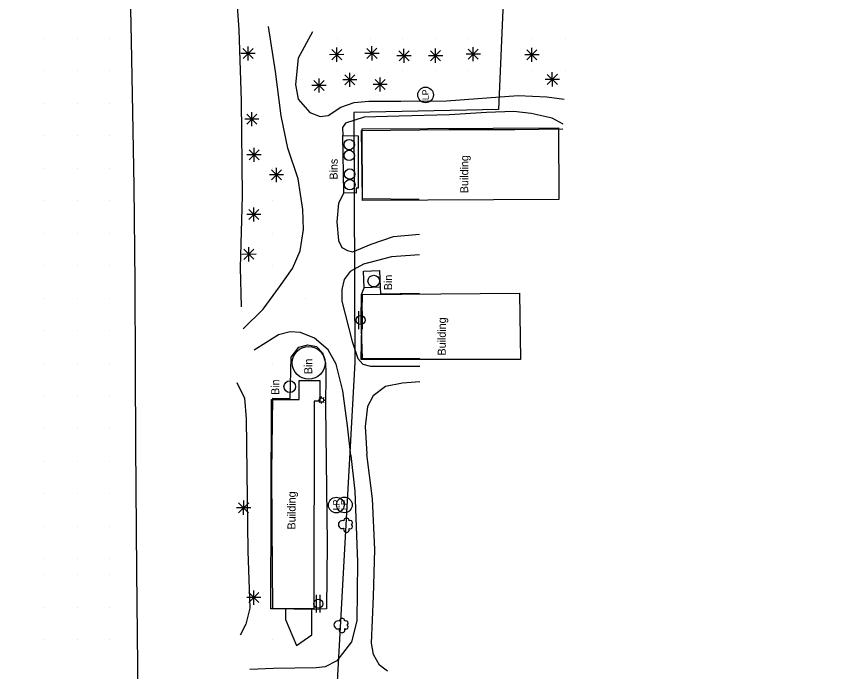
# Model space of a CAD drawing. Extents: x 19528164 to 19545171, y 7585743 to 7602745.
# Drawn here: x 19538887.4 to 19539384.5, y 7590990.4 to 7591393.6 of the extents above; entities that cross this region are included whole.
import ezdxf

# ---------------------------------------------------------------- set-up
doc = ezdxf.new("R2010")
doc.units = 0
for name, color, linetype in [('PhoAgStruc', 7, 'Continuous'), ('PhoBreakLine', 7, 'Continuous'), ('PhoBuilding', 7, 'Continuous'), ('PhoConcreteSlab', 7, 'Continuous'), ('PhoFence', 7, 'Continuous'), ('PhoISAEPoints', 7, 'Continuous'), ('PhoNotesDesign', 7, 'Continuous'), ('PhoSurveyLimits', 7, 'Continuous'), ('PhoVegetation', 7, 'Continuous'), ('SurNaturalCells', 7, 'Continuous'), ('SurROWRail', 7, 'Continuous')]:
    doc.layers.add(name, color=color, linetype=linetype)

msp = doc.modelspace()

# ---------------------------------------------------------------- linework, layer by layer
at = {"layer": 'PhoAgStruc'}
for centre, radius in [((19539092.17, 7591314.62), 3.21), ((19539092.15, 7591307.99), 3.21), ((19539092.49, 7591296.47), 3.21), ((19539092.51, 7591289.96), 3.21), ((19539107.24, 7591230.71), 3.58), ((19539067.23, 7591180.39), 10.06), ((19539055.61, 7591165.75), 3.58)]:
    msp.add_circle(centre, radius, dxfattribs=at)
at = {"layer": 'PhoBreakLine'}
for points in [[(19539025.94, 7591214.81), (19539025.21, 7591239.13), (19539026.55, 7591282.93), (19539025.96, 7591341.48), (19539024.58, 7591385.28), (19539021.31, 7591432.04), (19539020.65, 7591488.25), (19539019.39, 7591531.16), (19539015.09, 7591568.39), (19539005.57, 7591605.31), (19538988.58, 7591634.8), (19538965.78, 7591663.6), (19538941.84, 7591687.62), (19538913.36, 7591707.64), (19538889.81, 7591717.59)], [(19538960.98, 7591129.76), (19538960.69, 7591177.17), (19538960.55, 7591229.68), (19538959.96, 7591288.96), (19538959.08, 7591334.58), (19538958.24, 7591378.21), (19538957.47, 7591418.01), (19538957.15, 7591460.19), (19538956.9, 7591507.6), (19538955.55, 7591540.34), (19538952.92, 7591562.95), (19538946.91, 7591580.96), (19538929.63, 7591609.56), (19538905.04, 7591635.92), (19538883.9, 7591650.01), (19538863.93, 7591658.15), (19538827.45, 7591669.97), (19538802.9, 7591674.09), (19538770.4, 7591676.06), (19538725.84, 7591674.84), (19538709.43, 7591674.53)], [(19539135.19, 7591280.88), (19539100.27, 7591281.24), (19539099.61, 7591323.38), (19539153.31, 7591323.86), (19539193.88, 7591324), (19539223.49, 7591324.32)], [(19539135.53, 7591182.89), (19539100.31, 7591183.14), (19539099.55, 7591207.12), (19539099.66, 7591222.34), (19539101.3, 7591226.6)], [(19539111.2, 7591227.01), (19539111.4, 7591222.94), (19539135.39, 7591223.21)], [(19539023.1, 7591168.25), (19539027.81, 7591158.74), (19539028.81, 7591145.93), (19539029.73, 7591064.5), (19539031.03, 7591029.45), (19539028.63, 7591019.72), (19539025.11, 7591012.9)], [(19538977.84, 7590689.62), (19538970.79, 7590726.93), (19538967.2, 7590763.47), (19538965.07, 7590800.31), (19538964.71, 7590837.65), (19538964.26, 7590895.44), (19538962.68, 7590956), (19538961.54, 7591052.07), (19538960.98, 7591129.76)]]:
    msp.add_lwpolyline(points, dxfattribs=at)
msp.add_lwpolyline([(19539070.74, 7591028.77), (19539045.14, 7591029.2), (19539044.87, 7591080.32), (19539044.62, 7591113.49), (19539045.16, 7591158.6), (19539055.92, 7591158.5), (19539056.4, 7591183.88), (19539061.07, 7591189.94), (19539066.64, 7591191.57), (19539072, 7591190.43), (19539075.63, 7591186.46), (19539077.6, 7591180.49), (19539077.82, 7591174.33), (19539077.58, 7591153.41), (19539078.61, 7591069.5), (19539078.22, 7591029.19)], close=True, dxfattribs=at)
at = {"layer": 'PhoBuilding'}
for points in [[(19539100.07, 7591324.27), (19539220.84, 7591324.99), (19539221.1, 7591280.9), (19539100.34, 7591280.18)], [(19539044.04, 7591029.12), (19539044.31, 7591157.92), (19539061.41, 7591157.89), (19539061.43, 7591169.52), (19539074.01, 7591169.5), (19539073.98, 7591156.75), (19539070.58, 7591156.76), (19539070.31, 7591029.07)]]:
    msp.add_lwpolyline(points, close=True, dxfattribs=at)
msp.add_lwpolyline([(19539100.08, 7591222.44), (19539196.77, 7591223.24), (19539197.34, 7591182.38), (19539099.5, 7591182.42), (19539100.34, 7591222.44)], dxfattribs=at)
at = {"layer": 'PhoConcreteSlab'}
for points in [[(19539088.76, 7591284.98), (19539088.21, 7591320.31), (19539097.61, 7591319.96), (19539097.72, 7591287.73), (19539096.49, 7591287.81), (19539096.33, 7591284.66)], [(19539101.3, 7591226.6), (19539101.01, 7591236.8), (19539110.78, 7591237.26), (19539111.2, 7591227.01)]]:
    msp.add_lwpolyline(points, close=True, dxfattribs=at)
at = {"layer": 'PhoFence'}
msp.add_lwpolyline([(19539052.91, 7591029.11), (19539052.93, 7591022.61), (19539059.73, 7591006.67), (19539069.17, 7591013.17), (19539069.16, 7591029.07)], dxfattribs=at)
at = {"layer": 'PhoISAEPoints'}
for p, q in [((19538905, 7591380), (19538905, 7591380)), ((19538925, 7591380), (19538925, 7591380)), ((19538945, 7591380), (19538945, 7591380)), ((19539085, 7591380), (19539085, 7591380)), ((19539105, 7591380), (19539105, 7591380)), ((19539125, 7591380), (19539125, 7591380)), ((19539145, 7591380), (19539145, 7591380)), ((19539165, 7591380), (19539165, 7591380)), ((19539185, 7591380), (19539185, 7591380)), ((19539205, 7591380), (19539205, 7591380)), ((19539225, 7591380), (19539225, 7591380)), ((19538905, 7591360), (19538905, 7591360)), ((19538925, 7591360), (19538925, 7591360)), ((19538945, 7591360), (19538945, 7591360)), ((19539085, 7591360), (19539085, 7591360)), ((19539105, 7591360), (19539105, 7591360)), ((19539125, 7591360), (19539125, 7591360)), ((19539145, 7591360), (19539145, 7591360)), ((19539165, 7591360), (19539165, 7591360)), ((19539185, 7591360), (19539185, 7591360)), ((19539205, 7591360), (19539205, 7591360)), ((19539225, 7591360), (19539225, 7591360)), ((19538905, 7591340), (19538905, 7591340)), ((19538925, 7591340), (19538925, 7591340)), ((19538945, 7591340), (19538945, 7591340)), ((19538905, 7591320), (19538905, 7591320)), ((19538925, 7591320), (19538925, 7591320)), ((19538945, 7591320), (19538945, 7591320)), ((19538905, 7591300), (19538905, 7591300)), ((19538925, 7591300), (19538925, 7591300)), ((19538945, 7591300), (19538945, 7591300)), ((19539045, 7591300), (19539045, 7591300)), ((19538905, 7591280), (19538905, 7591280)), ((19538925, 7591280), (19538925, 7591280)), ((19538945, 7591280), (19538945, 7591280)), ((19539045, 7591280), (19539045, 7591280)), ((19538905, 7591260), (19538905, 7591260)), ((19538925, 7591260), (19538925, 7591260)), ((19538945, 7591260), (19538945, 7591260)), ((19539045, 7591260), (19539045, 7591260)), ((19538905, 7591240), (19538905, 7591240)), ((19538925, 7591240), (19538925, 7591240)), ((19538945, 7591240), (19538945, 7591240)), ((19539045, 7591240), (19539045, 7591240)), ((19538905, 7591220), (19538905, 7591220)), ((19538925, 7591220), (19538925, 7591220)), ((19538945, 7591220), (19538945, 7591220)), ((19539065, 7591220), (19539065, 7591220)), ((19538905, 7591200), (19538905, 7591200)), ((19538925, 7591200), (19538925, 7591200)), ((19538945, 7591200), (19538945, 7591200)), ((19538905, 7591180), (19538905, 7591180)), ((19538925, 7591180), (19538925, 7591180)), ((19538945, 7591180), (19538945, 7591180)), ((19539045, 7591180), (19539045, 7591180)), ((19538905, 7591160), (19538905, 7591160)), ((19538925, 7591160), (19538925, 7591160)), ((19538945, 7591160), (19538945, 7591160)), ((19538905, 7591140), (19538905, 7591140)), ((19538925, 7591140), (19538925, 7591140)), ((19538945, 7591140), (19538945, 7591140)), ((19538905, 7591120), (19538905, 7591120)), ((19538925, 7591120), (19538925, 7591120)), ((19538945, 7591120), (19538945, 7591120)), ((19538905, 7591100), (19538905, 7591100)), ((19538925, 7591100), (19538925, 7591100)), ((19538945, 7591100), (19538945, 7591100)), ((19538905, 7591080), (19538905, 7591080)), ((19538925, 7591080), (19538925, 7591080)), ((19538945, 7591080), (19538945, 7591080)), ((19538905, 7591060), (19538905, 7591060)), ((19538925, 7591060), (19538925, 7591060)), ((19538945, 7591060), (19538945, 7591060)), ((19538905, 7591050), (19538905, 7591050)), ((19538925, 7591050), (19538925, 7591050)), ((19538945, 7591050), (19538945, 7591050)), ((19538905, 7591030), (19538905, 7591030)), ((19538925, 7591030), (19538925, 7591030)), ((19538945, 7591030), (19538945, 7591030)), ((19538905, 7591010), (19538905, 7591010)), ((19538925, 7591010), (19538925, 7591010)), ((19538945, 7591010), (19538945, 7591010)), ((19539045, 7591010), (19539045, 7591010)), ((19539065, 7591010), (19539065, 7591010))]:
    msp.add_line(p, q, dxfattribs=at)
at = {"layer": 'PhoSurveyLimits'}
msp.add_lwpolyline([(19543262.35, 7595683.22), (19543257.95, 7595379.65), (19542419.97, 7595255.07), (19541879.23, 7595109.17), (19539317.07, 7592404.33), (19539317.07, 7592404.33), (19539199.99, 7591704.87), (19539183.97, 7591336.2), (19539095.01, 7591334.37), (19539095.54, 7591180.74), (19539068.71, 7590695.4), (19538920.46, 7590698.41), (19538798.64, 7591142.79), (19538688.52, 7591615.61), (19537853.91, 7591634.47), (19537374.94, 7591324.13)], dxfattribs=at)
at = {"layer": 'PhoVegetation'}
for p, q in [((19539029.96, 7591366.25), (19539029.93, 7591375)), ((19539084.47, 7591365.55), (19539084.44, 7591374.3)), ((19539106.16, 7591366.35), (19539106.13, 7591375.1)), ((19539168.41, 7591365.88), (19539168.38, 7591374.63)), ((19539204.47, 7591365.46), (19539204.44, 7591374.21)), ((19539034.32, 7591370.64), (19539025.57, 7591370.61)), ((19539033.05, 7591367.54), (19539026.84, 7591373.71)), ((19539033.02, 7591373.73), (19539026.86, 7591367.52)), ((19539029.94, 7591370.63), (19539029.94, 7591370.63)), ((19539088.83, 7591369.94), (19539080.09, 7591369.91)), ((19539087.56, 7591366.84), (19539081.36, 7591373.01)), ((19539087.54, 7591373.03), (19539081.38, 7591366.82)), ((19539084.46, 7591369.92), (19539084.46, 7591369.92)), ((19539110.52, 7591370.74), (19539101.77, 7591370.71)), ((19539109.25, 7591367.64), (19539103.04, 7591373.8)), ((19539109.22, 7591373.83), (19539103.06, 7591367.62)), ((19539106.14, 7591370.72), (19539106.14, 7591370.72)), ((19539130.21, 7591369.23), (19539121.46, 7591369.2)), ((19539128.94, 7591366.14), (19539122.73, 7591372.3)), ((19539128.92, 7591372.32), (19539122.76, 7591366.11)), ((19539125.85, 7591364.84), (19539125.82, 7591373.59)), ((19539125.84, 7591369.22), (19539125.84, 7591369.22)), ((19539149.6, 7591369.3), (19539140.85, 7591369.27)), ((19539148.33, 7591366.2), (19539142.12, 7591372.37)), ((19539148.31, 7591372.39), (19539142.15, 7591366.18)), ((19539145.24, 7591364.91), (19539145.21, 7591373.66)), ((19539145.23, 7591369.28), (19539145.23, 7591369.28)), ((19539172.77, 7591370.27), (19539164.02, 7591370.24)), ((19539171.5, 7591367.18), (19539165.3, 7591373.34)), ((19539171.48, 7591373.36), (19539165.32, 7591367.16)), ((19539168.4, 7591370.26), (19539168.4, 7591370.26)), ((19539208.83, 7591369.85), (19539200.09, 7591369.82)), ((19539207.56, 7591366.75), (19539201.36, 7591372.91)), ((19539207.54, 7591372.93), (19539201.38, 7591366.73)), ((19539204.46, 7591369.83), (19539204.46, 7591369.83)), ((19539217.03, 7591350.36), (19539217, 7591359.11)), ((19539073.61, 7591346.59), (19539073.58, 7591355.34)), ((19539096.88, 7591354.49), (19539088.13, 7591354.46)), ((19539095.61, 7591351.39), (19539089.4, 7591357.56)), ((19539095.59, 7591357.58), (19539089.43, 7591351.37)), ((19539092.52, 7591350.1), (19539092.49, 7591358.85)), ((19539092.51, 7591354.47), (19539092.51, 7591354.47)), ((19539114.29, 7591348.52), (19539108.08, 7591354.69)), ((19539114.27, 7591354.71), (19539108.1, 7591348.5)), ((19539111.2, 7591347.23), (19539111.17, 7591355.98)), ((19539221.39, 7591354.75), (19539212.64, 7591354.72)), ((19539220.12, 7591351.66), (19539213.91, 7591357.82)), ((19539220.09, 7591357.84), (19539213.93, 7591351.63)), ((19539217.01, 7591354.74), (19539217.01, 7591354.74)), ((19539077.97, 7591350.98), (19539069.22, 7591350.95)), ((19539076.7, 7591347.88), (19539070.49, 7591354.05)), ((19539076.68, 7591354.07), (19539070.52, 7591347.86)), ((19539073.6, 7591350.96), (19539073.6, 7591350.96)), ((19539115.56, 7591351.62), (19539106.81, 7591351.59)), ((19539111.19, 7591351.6), (19539111.19, 7591351.6)), ((19539032.31, 7591325.91), (19539032.28, 7591334.66)), ((19539036.67, 7591330.3), (19539027.92, 7591330.27)), ((19539035.4, 7591327.2), (19539029.19, 7591333.36)), ((19539035.38, 7591333.38), (19539029.21, 7591327.18)), ((19539032.3, 7591330.28), (19539032.3, 7591330.28)), ((19539036.75, 7591305.26), (19539030.54, 7591311.43)), ((19539036.73, 7591311.45), (19539030.57, 7591305.24)), ((19539033.66, 7591303.97), (19539033.63, 7591312.72)), ((19539038.02, 7591308.36), (19539029.27, 7591308.33)), ((19539033.65, 7591308.34), (19539033.65, 7591308.34)), ((19539047.48, 7591291.6), (19539047.45, 7591300.35)), ((19539051.84, 7591295.99), (19539043.09, 7591295.96)), ((19539050.57, 7591292.89), (19539044.36, 7591299.06)), ((19539050.55, 7591299.08), (19539044.39, 7591292.87)), ((19539047.47, 7591295.98), (19539047.47, 7591295.98)), ((19539036.62, 7591268.52), (19539030.42, 7591274.69)), ((19539036.6, 7591274.71), (19539030.44, 7591268.5)), ((19539033.54, 7591267.23), (19539033.5, 7591275.98)), ((19539037.89, 7591271.62), (19539029.15, 7591271.59)), ((19539033.52, 7591271.6), (19539033.52, 7591271.6)), ((19539033.61, 7591244.06), (19539027.4, 7591250.23)), ((19539033.58, 7591250.25), (19539027.42, 7591244.04)), ((19539030.52, 7591242.77), (19539030.49, 7591251.52)), ((19539034.87, 7591247.16), (19539026.13, 7591247.13)), ((19539030.5, 7591247.14), (19539030.5, 7591247.14)), ((19539027.21, 7591086.9), (19539027.26, 7591095.65)), ((19539031.61, 7591091.25), (19539022.86, 7591091.3)), ((19539030.35, 7591094.35), (19539024.13, 7591088.2)), ((19539030.31, 7591088.17), (19539024.16, 7591094.39)), ((19539027.24, 7591091.28), (19539027.24, 7591091.28)), ((19539037.86, 7591036.03), (19539029.11, 7591036.07)), ((19539036.59, 7591039.13), (19539030.38, 7591032.97)), ((19539036.56, 7591032.94), (19539030.41, 7591039.16)), ((19539033.46, 7591031.68), (19539033.51, 7591040.42)), ((19539033.49, 7591036.05), (19539033.49, 7591036.05))]:
    msp.add_line(p, q, dxfattribs=at)
for centre, radius, start, end in [((19539087.96, 7591080.93), 2.46, 67.8949, 291.4847), ((19539090.49, 7591083.31), 1.6, 355.688, 183.6916), ((19539092.88, 7591079.68), 1.34, 232.44, 65.0122), ((19539092.86, 7591082.09), 1.34, 296.214, 125.0932), ((19539090.46, 7591077.9), 1.76, 155.1722, 24.2074), ((19539085.25, 7591019.24), 2.46, 67.8949, 291.4847), ((19539087.78, 7591021.62), 1.6, 355.688, 183.6916), ((19539090.14, 7591020.41), 1.34, 296.214, 125.0932), ((19539087.75, 7591016.21), 1.76, 155.1722, 24.2074), ((19539090.17, 7591017.99), 1.34, 232.44, 65.0122)]:
    msp.add_arc(centre, radius, start, end, dxfattribs=at)
at = {"layer": 'SurNaturalCells'}
for p, q in [((19539098.15, 7591201.19), (19539098.11, 7591212.18)), ((19539100.35, 7591201.19), (19539100.31, 7591212.19)), ((19539073, 7591157.52), (19539073.82, 7591157.51)), ((19539073.63, 7591155.97), (19539074.21, 7591156.55)), ((19539074.22, 7591158.47), (19539073.65, 7591159.05)), ((19539075.17, 7591155.33), (19539075.17, 7591156.14)), ((19539075.18, 7591158.86), (19539075.19, 7591159.68)), ((19539076.71, 7591155.96), (19539076.13, 7591156.54)), ((19539076.14, 7591158.46), (19539076.72, 7591159.03)), ((19539076.54, 7591157.5), (19539077.35, 7591157.49)), ((19539072.01, 7591026.79), (19539072.07, 7591037.79)), ((19539074.21, 7591026.78), (19539074.27, 7591037.78))]:
    msp.add_line(p, q, dxfattribs=at)
for centre, radius in [((19539139.06, 7591345.2), 4.8), ((19539099.23, 7591206.69), 2.76), ((19539075.18, 7591157.5), 1.36), ((19539084.18, 7591092.9), 4.8), ((19539089.16, 7591093.05), 4.8), ((19539073.14, 7591032.28), 2.76)]:
    msp.add_circle(centre, radius, dxfattribs=at)
at = {"layer": 'SurROWRail'}
for points in [[(19539026.85, 7591201.37), (19539039.22, 7591213.45), (19539049.3, 7591227.09), (19539057.38, 7591238.43), (19539061.98, 7591249.25), (19539063.97, 7591262.44), (19539063.59, 7591274.64), (19539060.67, 7591293.47), (19539054.44, 7591312.5), (19539050.21, 7591332.26), (19539046.84, 7591359.5), (19539042.49, 7591387.21)], [(19539069.67, 7591383.9), (19539060.71, 7591367.84), (19539059.15, 7591351.55), (19539060.75, 7591342.63), (19539067.88, 7591334.32), (19539074.22, 7591331.96), (19539079.24, 7591332.44), (19539087.05, 7591337.57), (19539095.24, 7591340.53), (19539104.17, 7591341.42), (19539123.94, 7591341.23), (19539151.88, 7591341.5), (19539195.96, 7591344.88), (19539213.7, 7591344.05), (19539224.29, 7591342.63)], [(19539223.62, 7591327.2), (19539216.81, 7591330.97), (19539204.04, 7591333.68), (19539193.32, 7591335.05), (19539176.61, 7591334.35), (19539153.87, 7591332.91), (19539122.83, 7591332.13), (19539101.27, 7591331.46), (19539089.93, 7591327.89), (19539088.03, 7591325.2), (19539088.21, 7591320.31)], [(19539088.76, 7591284.98), (19539085.51, 7591278.59), (19539084.61, 7591267.06), (19539085.46, 7591255.71), (19539087.69, 7591251.25), (19539091.01, 7591249.39), (19539094.42, 7591248.68), (19539105.54, 7591253.4), (19539119.34, 7591258), (19539135.26, 7591259.56)], [(19539135.31, 7591246.74), (19539118.24, 7591245.62), (19539100.86, 7591241.05), (19539092.76, 7591236.52), (19539089.07, 7591231.7), (19539087.65, 7591225.53), (19539087.63, 7591218.3), (19539094.05, 7591193.61), (19539097.45, 7591183.04), (19539100.48, 7591179.65), (19539105.29, 7591178.35), (19539135.54, 7591178.31)], [(19539093.11, 7591123.42), (19539091, 7591141.62), (19539088.16, 7591163.17), (19539084.19, 7591179.61), (19539079.14, 7591188.35), (19539070.74, 7591195.63), (19539062.14, 7591199.01), (19539055.85, 7591199.54), (19539048.62, 7591197.56), (19539040.82, 7591192.72), (19539033.73, 7591188.13)], [(19539135.58, 7591168.75), (19539124.97, 7591167.91), (19539114.39, 7591165.75), (19539106.84, 7591160.15), (19539103.38, 7591153.59), (19539101.98, 7591141.25), (19539102.89, 7591124.14)], [(19539093.11, 7591123.42), (19539095.62, 7591101.51), (19539097.22, 7591057.92), (19539096.86, 7591021.77), (19539093.51, 7591008.78), (19539084.44, 7590997.14), (19539077.44, 7590993.35), (19539071.78, 7590992.82), (19539045.5, 7590992.41), (19539031.12, 7590991.86)], [(19539115.61, 7590990.75), (19539110.78, 7590994.4), (19539107.11, 7591001.1), (19539105.92, 7591007.91), (19539107.14, 7591036.73), (19539107.97, 7591065.56), (19539106.4, 7591096.78), (19539102.89, 7591124.14)]]:
    msp.add_lwpolyline(points, dxfattribs=at)

# ---------------------------------------------------------------- texts
at = {"layer": 'PhoNotesDesign'}
for s, p in [('Bins', (19539084.99, 7591293.09)), ('Building', (19539165.27, 7591284.72)), ('Bin', (19539118.49, 7591225.04)), ('Building', (19539151.46, 7591184.91)), ('Bin', (19539069.39, 7591173.46)), ('Bin', (19539049.11, 7591160.63)), ('Building', (19539059.09, 7591077.9))]:
    msp.add_text(s, height=4.92, rotation=89.6898, dxfattribs=at).set_placement(p)
at = {"layer": 'SurNaturalCells'}
for rotation, p in [(90.1997, (19539141.07, 7591342.02)), (89.6898, (19539086.16, 7591089.72)), (89.6898, (19539091.14, 7591089.86))]:
    msp.add_text('LP', height=3.999, rotation=rotation, dxfattribs=at).set_placement(p)

doc.saveas('drawing.dxf')
